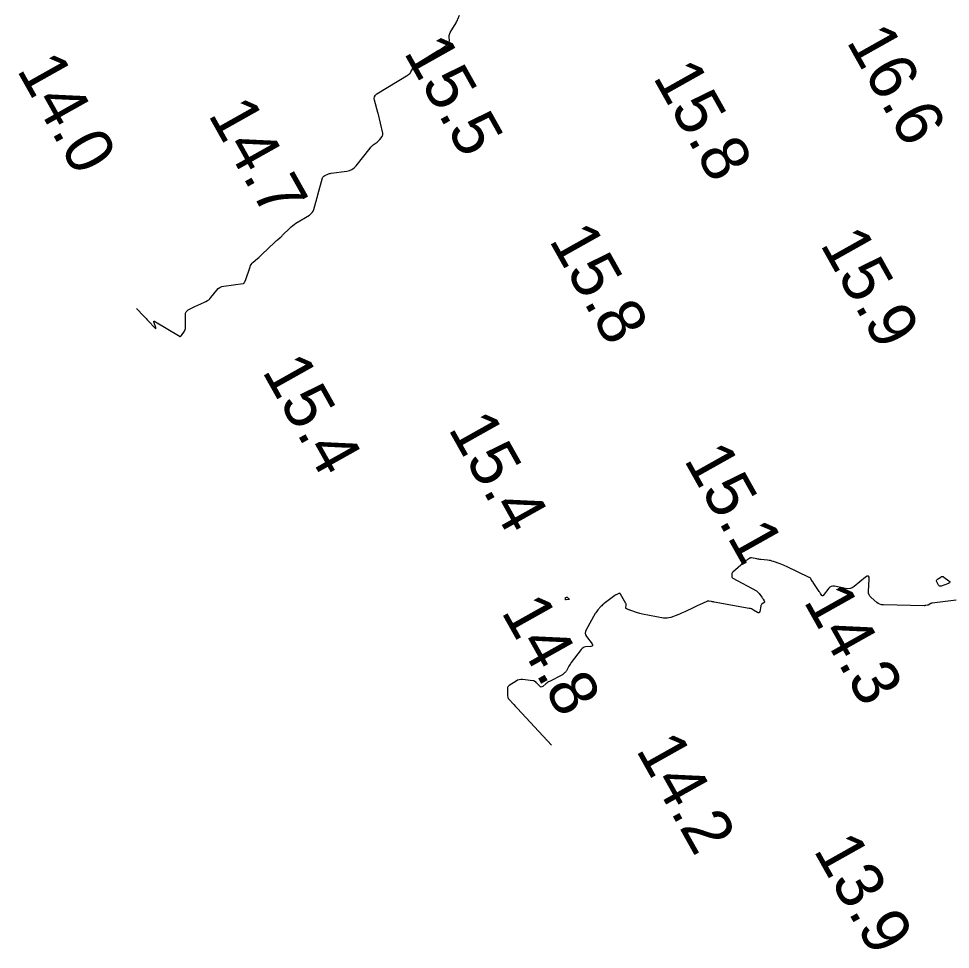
# Model space of a CAD drawing. Extents: x 1023796 to 1112670, y 656573 to 837340.
# Drawn here: x 1108543.8 to 1108641.6, y 682809.7 to 682907.4 of the extents above; entities that cross this region are included whole.
import ezdxf

# ---------------------------------------------------------------- set-up
doc = ezdxf.new("R2010")
doc.units = 0
doc.layers.add('V-CHAN-CONT-15FT', color=7, linetype='Continuous')
doc.layers.add('V-TOPO-SOUN', color=7, linetype='Continuous')

msp = doc.modelspace()

# ---------------------------------------------------------------- linework, layer by layer
at = {"layer": 'V-CHAN-CONT-15FT'}
for points in [[(1108556.129, 682876.967), (1108556.9, 682876.167), (1108557.028, 682876.033), (1108557.156, 682875.899), (1108557.283, 682875.764), (1108557.409, 682875.629), (1108558.069, 682874.922), (1108558.141, 682874.854), (1108558.18, 682874.841), (1108558.187, 682874.882), (1108558.16, 682874.977), (1108557.99, 682875.465), (1108557.966, 682875.563), (1108557.981, 682875.615), (1108558.034, 682875.619), (1108558.126, 682875.577), (1108560.572, 682874.12), (1108560.586, 682874.111), (1108560.6, 682874.101), (1108560.613, 682874.09), (1108560.626, 682874.078), (1108560.674, 682874.028), (1108560.686, 682874.019), (1108560.699, 682874.015), (1108560.712, 682874.016), (1108560.727, 682874.022), (1108560.802, 682874.071), (1108560.819, 682874.083), (1108560.834, 682874.096), (1108560.848, 682874.111), (1108560.861, 682874.127), (1108561.184, 682874.58), (1108561.235, 682874.664), (1108561.27, 682874.752), (1108561.291, 682874.844), (1108561.298, 682874.942), (1108561.28, 682876.313), (1108561.298, 682876.474), (1108561.354, 682876.611), (1108561.45, 682876.724), (1108561.584, 682876.813), (1108562.203, 682877.125), (1108562.356, 682877.201), (1108562.51, 682877.276), (1108562.664, 682877.349), (1108562.819, 682877.421), (1108563.441, 682877.706), (1108563.59, 682877.785), (1108563.727, 682877.88), (1108563.851, 682877.99), (1108563.964, 682878.117), (1108564.582, 682878.898), (1108564.731, 682879.054), (1108564.9, 682879.175), (1108565.091, 682879.259), (1108565.301, 682879.308), (1108567.346, 682879.587), (1108567.357, 682879.589), (1108567.368, 682879.591), (1108567.379, 682879.595), (1108567.389, 682879.599), (1108567.43, 682879.618), (1108567.44, 682879.623), (1108567.448, 682879.63), (1108567.455, 682879.638), (1108567.461, 682879.647), (1108567.533, 682879.782), (1108567.547, 682879.808), (1108567.559, 682879.835), (1108567.57, 682879.862), (1108567.58, 682879.889), (1108568.067, 682881.323), (1108568.125, 682881.463), (1108568.199, 682881.592), (1108568.29, 682881.71), (1108568.398, 682881.817), (1108568.861, 682882.222), (1108568.976, 682882.324), (1108569.09, 682882.427), (1108569.204, 682882.532), (1108569.316, 682882.637), (1108570.681, 682883.935), (1108570.746, 682883.996), (1108570.812, 682884.056), (1108570.88, 682884.116), (1108570.948, 682884.174), (1108571.222, 682884.404), (1108571.29, 682884.463), (1108571.357, 682884.523), (1108571.422, 682884.584), (1108571.486, 682884.646), (1108572.236, 682885.395), (1108572.386, 682885.537), (1108572.543, 682885.668), (1108572.708, 682885.79), (1108572.88, 682885.903), (1108574.302, 682886.772), (1108574.458, 682886.888), (1108574.585, 682887.025), (1108574.683, 682887.184), (1108574.752, 682887.365), (1108574.971, 682888.132), (1108575.026, 682888.324), (1108575.081, 682888.516), (1108575.135, 682888.708), (1108575.189, 682888.9), (1108575.687, 682890.664), (1108575.718, 682890.745), (1108575.764, 682890.813), (1108575.825, 682890.868), (1108575.899, 682890.912), (1108576.226, 682891.061), (1108576.309, 682891.095), (1108576.394, 682891.123), (1108576.48, 682891.144), (1108576.568, 682891.16), (1108578.215, 682891.386), (1108578.505, 682891.453), (1108578.766, 682891.57), (1108578.999, 682891.737), (1108579.202, 682891.953), (1108580.659, 682893.81), (1108580.735, 682893.9), (1108580.816, 682893.984), (1108580.903, 682894.062), (1108580.996, 682894.134), (1108581.408, 682894.432), (1108581.486, 682894.493), (1108581.559, 682894.559), (1108581.626, 682894.631), (1108581.688, 682894.708), (1108581.925, 682895.028), (1108581.974, 682895.11), (1108582.003, 682895.196), (1108582.011, 682895.287), (1108581.998, 682895.382), (1108581.497, 682897.482), (1108581.495, 682897.49), (1108581.492, 682897.499), (1108581.484, 682897.515), (1108581.481, 682897.523), (1108581.479, 682897.531), (1108581.121, 682898.816), (1108581.092, 682899.019), (1108581.126, 682899.198), (1108581.223, 682899.352), (1108581.382, 682899.481), (1108584.66, 682901.494), (1108584.748, 682901.556), (1108584.825, 682901.627), (1108584.893, 682901.708), (1108584.951, 682901.799), (1108585.254, 682902.349), (1108585.259, 682902.36), (1108585.262, 682902.372), (1108585.262, 682902.384), (1108585.26, 682902.397), (1108585.247, 682902.448), (1108585.245, 682902.459), (1108585.247, 682902.47), (1108585.253, 682902.479), (1108585.262, 682902.486), (1108587.758, 682904.002), (1108587.884, 682904.08), (1108588.009, 682904.159), (1108588.134, 682904.24), (1108588.257, 682904.322), (1108588.807, 682904.694), (1108588.889, 682904.763), (1108588.946, 682904.845), (1108588.98, 682904.94), (1108588.989, 682905.046), (1108588.979, 682905.499), (1108588.983, 682905.61), (1108589.003, 682905.717), (1108589.037, 682905.821), (1108589.087, 682905.921), (1108589.688, 682906.958), (1108589.742, 682907.054), (1108589.793, 682907.153), (1108589.84, 682907.253), (1108589.884, 682907.355), (1108590.052, 682907.765)], [(1108642.187, 682846.349), (1108639.675, 682846.034), (1108639.631, 682846.026), (1108639.588, 682846.013), (1108639.548, 682845.996), (1108639.509, 682845.974), (1108639.356, 682845.876), (1108639.317, 682845.854), (1108639.277, 682845.835), (1108639.235, 682845.821), (1108639.191, 682845.81), (1108639.004, 682845.773), (1108638.957, 682845.765), (1108638.911, 682845.76), (1108638.864, 682845.757), (1108638.818, 682845.756), (1108634.551, 682845.839), (1108634.36, 682845.858), (1108634.181, 682845.908), (1108634.013, 682845.989), (1108633.858, 682846.101), (1108633.258, 682846.608), (1108633.128, 682846.744), (1108633.039, 682846.897), (1108632.99, 682847.067), (1108632.982, 682847.255), (1108633.062, 682848.537), (1108633.05, 682848.759), (1108632.98, 682848.867), (1108632.851, 682848.861), (1108632.663, 682848.742), (1108631.485, 682847.784), (1108631.276, 682847.647), (1108631.054, 682847.565), (1108630.819, 682847.536), (1108630.571, 682847.562), (1108629.399, 682847.806), (1108629.229, 682847.82), (1108629.075, 682847.789), (1108628.939, 682847.713), (1108628.818, 682847.592), (1108628.226, 682846.828), (1108628.187, 682846.791), (1108628.15, 682846.779), (1108628.113, 682846.793), (1108628.077, 682846.832), (1108627.934, 682847.041), (1108627.899, 682847.094), (1108627.864, 682847.146), (1108627.829, 682847.199), (1108627.794, 682847.252), (1108627.19, 682848.186), (1108627.183, 682848.197), (1108627.175, 682848.208), (1108627.167, 682848.219), (1108627.158, 682848.229), (1108627.123, 682848.27), (1108627.114, 682848.28), (1108627.106, 682848.291), (1108627.098, 682848.302), (1108627.091, 682848.313), (1108626.919, 682848.585), (1108626.885, 682848.631), (1108626.846, 682848.672), (1108626.801, 682848.706), (1108626.752, 682848.734), (1108624.379, 682849.871), (1108624.216, 682849.946), (1108624.052, 682850.017), (1108623.886, 682850.084), (1108623.718, 682850.146), (1108623, 682850.399), (1108622.851, 682850.447), (1108622.701, 682850.486), (1108622.548, 682850.515), (1108622.393, 682850.535), (1108621.674, 682850.607), (1108621.567, 682850.619), (1108621.46, 682850.633), (1108621.353, 682850.65), (1108621.246, 682850.668), (1108620.714, 682850.766), (1108620.662, 682850.771), (1108620.612, 682850.767), (1108620.563, 682850.753), (1108620.516, 682850.731), (1108620.332, 682850.621), (1108620.286, 682850.593), (1108620.242, 682850.563), (1108620.199, 682850.531), (1108620.158, 682850.497), (1108618.738, 682849.293), (1108618.696, 682849.25), (1108618.667, 682849.202), (1108618.649, 682849.148), (1108618.643, 682849.089), (1108618.643, 682848.842), (1108618.65, 682848.784), (1108618.67, 682848.734), (1108618.704, 682848.692), (1108618.752, 682848.658), (1108621.218, 682847.3), (1108621.302, 682847.247), (1108621.378, 682847.186), (1108621.447, 682847.117), (1108621.509, 682847.04), (1108621.79, 682846.645), (1108621.824, 682846.598), (1108621.856, 682846.55), (1108621.888, 682846.501), (1108621.92, 682846.452), (1108622.044, 682846.255), (1108622.066, 682846.208), (1108622.068, 682846.164), (1108622.051, 682846.123), (1108622.015, 682846.086), (1108621.794, 682845.914), (1108621.747, 682845.871), (1108621.71, 682845.821), (1108621.683, 682845.765), (1108621.666, 682845.703), (1108621.562, 682845.146), (1108621.531, 682845.054), (1108621.48, 682845.005), (1108621.411, 682845.001), (1108621.322, 682845.041), (1108620.905, 682845.304), (1108620.8, 682845.364), (1108620.692, 682845.412), (1108620.579, 682845.45), (1108620.462, 682845.476), (1108616.77, 682846.141), (1108616.705, 682846.152), (1108616.64, 682846.163), (1108616.575, 682846.174), (1108616.509, 682846.185), (1108616.248, 682846.227), (1108616.184, 682846.232), (1108616.12, 682846.229), (1108616.058, 682846.215), (1108615.998, 682846.192), (1108615.226, 682845.835), (1108615.078, 682845.766), (1108614.929, 682845.697), (1108614.781, 682845.627), (1108614.632, 682845.558), (1108613.704, 682845.123), (1108613.522, 682845.04), (1108613.339, 682844.96), (1108613.154, 682844.884), (1108612.968, 682844.811), (1108612.221, 682844.525), (1108612.033, 682844.467), (1108611.842, 682844.437), (1108611.649, 682844.433), (1108611.454, 682844.457), (1108609.272, 682844.871), (1108609.132, 682844.9), (1108608.994, 682844.933), (1108608.858, 682844.972), (1108608.722, 682845.015), (1108608.018, 682845.253), (1108607.965, 682845.271), (1108607.913, 682845.289), (1108607.862, 682845.309), (1108607.811, 682845.33), (1108607.606, 682845.413), (1108607.562, 682845.438), (1108607.534, 682845.472), (1108607.52, 682845.514), (1108607.522, 682845.564), (1108607.558, 682845.781), (1108607.562, 682845.835), (1108607.558, 682845.887), (1108607.544, 682845.937), (1108607.522, 682845.986), (1108606.963, 682846.982), (1108606.928, 682847.026), (1108606.888, 682847.051), (1108606.84, 682847.055), (1108606.787, 682847.04), (1108606.558, 682846.937), (1108606.501, 682846.91), (1108606.447, 682846.88), (1108606.394, 682846.847), (1108606.342, 682846.811), (1108605.246, 682845.995), (1108605.152, 682845.921), (1108605.063, 682845.843), (1108604.978, 682845.759), (1108604.897, 682845.671), (1108604.583, 682845.309), (1108604.507, 682845.217), (1108604.436, 682845.121), (1108604.369, 682845.022), (1108604.308, 682844.92), (1108603.348, 682843.218), (1108603.274, 682843.038), (1108603.256, 682842.861), (1108603.294, 682842.687), (1108603.389, 682842.517), (1108603.96, 682841.735), (1108604.016, 682841.632), (1108604.015, 682841.555), (1108603.958, 682841.504), (1108603.844, 682841.478), (1108603.276, 682841.425), (1108603.141, 682841.399), (1108603.02, 682841.348), (1108602.914, 682841.271), (1108602.821, 682841.17), (1108601.789, 682839.792), (1108601.722, 682839.7), (1108601.659, 682839.606), (1108601.599, 682839.51), (1108601.542, 682839.412), (1108601.27, 682838.924), (1108601.238, 682838.872), (1108601.202, 682838.824), (1108601.162, 682838.778), (1108601.118, 682838.736), (1108600.934, 682838.575), (1108600.887, 682838.537), (1108600.838, 682838.501), (1108600.787, 682838.469), (1108600.733, 682838.44), (1108599.484, 682837.808), (1108599.387, 682837.756), (1108599.294, 682837.698), (1108599.205, 682837.634), (1108599.119, 682837.565), (1108598.785, 682837.277), (1108598.703, 682837.224), (1108598.623, 682837.21), (1108598.545, 682837.234), (1108598.47, 682837.297), (1108598.135, 682837.668), (1108598.05, 682837.747), (1108597.955, 682837.808), (1108597.85, 682837.85), (1108597.736, 682837.872), (1108596.664, 682837.993), (1108596.488, 682837.998), (1108596.319, 682837.975), (1108596.156, 682837.922), (1108596, 682837.84), (1108595.261, 682837.375), (1108595.183, 682837.313), (1108595.127, 682837.238), (1108595.093, 682837.151), (1108595.081, 682837.052), (1108595.077, 682836.524), (1108595.078, 682836.471), (1108595.081, 682836.419), (1108595.087, 682836.368), (1108595.095, 682836.316), (1108595.134, 682836.111), (1108595.147, 682836.061), (1108595.166, 682836.014), (1108595.192, 682835.971), (1108595.225, 682835.931), (1108595.748, 682835.371), (1108595.946, 682835.159), (1108596.144, 682834.947), (1108599.716, 682831.121)]]:
    msp.add_lwpolyline(points, dxfattribs=at)
for points in [[(1108640.738, 682848.823), (1108640.821, 682848.806), (1108640.903, 682848.76), (1108641.428, 682848.366), (1108641.512, 682848.285), (1108641.533, 682848.213), (1108641.492, 682848.15), (1108641.388, 682848.097), (1108640.605, 682847.817), (1108640.522, 682847.799), (1108640.449, 682847.81), (1108640.388, 682847.85), (1108640.337, 682847.919), (1108640.157, 682848.251), (1108640.128, 682848.331), (1108640.129, 682848.403), (1108640.161, 682848.468), (1108640.223, 682848.525), (1108640.571, 682848.766), (1108640.655, 682848.809)], [(1108601.334, 682846.663), (1108601.351, 682846.656), (1108601.367, 682846.644), (1108601.523, 682846.49), (1108601.545, 682846.462), (1108601.549, 682846.44), (1108601.533, 682846.424), (1108601.5, 682846.413), (1108601.232, 682846.366), (1108601.205, 682846.366), (1108601.185, 682846.374), (1108601.174, 682846.392), (1108601.171, 682846.419), (1108601.175, 682846.569), (1108601.178, 682846.589), (1108601.186, 682846.605), (1108601.198, 682846.618), (1108601.216, 682846.627), (1108601.296, 682846.659), (1108601.316, 682846.664)]]:
    msp.add_lwpolyline(points, close=True, dxfattribs=at)

# ---------------------------------------------------------------- texts
at = {"layer": 'V-TOPO-SOUN'}
for s, p in [('16.6 ', (1108630.605, 682905.015)), ('15.5 ', (1108584.139, 682903.868)), ('14.0 ', (1108543.525, 682902.026)), ('15.8 ', (1108610.292, 682901.263)), ('14.7 ', (1108563.602, 682897.333)), ('15.8 ', (1108599.392, 682884.143)), ('15.9 ', (1108627.842, 682883.713)), ('15.4 ', (1108569.272, 682870.393)), ('15.4 ', (1108588.802, 682864.353)), ('15.1 ', (1108613.548, 682861.087)), ('14.3 ', (1108626.102, 682846.243)), ('14.8 ', (1108594.372, 682845.133)), ('14.2 ', (1108608.512, 682830.633)), ('13.9 ', (1108627.152, 682820.103))]:
    msp.add_text(s, height=5, rotation=299.30014, dxfattribs=at).set_placement(p)

doc.saveas('drawing.dxf')
